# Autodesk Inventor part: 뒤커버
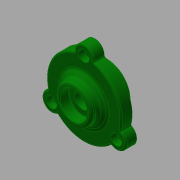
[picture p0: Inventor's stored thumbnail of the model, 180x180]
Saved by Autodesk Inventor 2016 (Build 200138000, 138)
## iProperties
Created: 2016-05
Part Number: 뒤커버
Document SubType Name: Modeling
Designer: mduedu
Density: 2.71 g/cm^3
Material: 알루미늄 6061
Appearance: 진녹색
Author: mduedu
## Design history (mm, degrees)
sketch "스케치1"
  geometry: C1 r 17.5 at (0, 0); C2 r 27.5 at (0, 0); 1 further point
  constraints: 2 centre point, 2 coincident
  dimensions: "d33" = 55 diameter of C2; "d34" = 35 diameter of C1
extrude "돌출1" new body sketch "스케치1" distance "d0" = 8; taper "d1" = 0 deg
extrude "돌출2" join sketch "스케치1" distance "d2" = 8; taper "d3" = 0 deg; dims "d35" = 9, "d36" = 0
sketch "스케치5"
  geometry: L1 (-27.5, 8)-(27.5, 8) reference; L2 (0, 0)-(0, 15); L3 (-27.5, 0)-(27.5, 0) reference; L4 (17.5, 8)-(0, 8); A1 r 25.375 centre (0, -10.375) between (17.5, 8) and (0, 15)
  constraints: 4 end point, 3 point on line, 2 point on circle, 1 centre point, 1 midpoint, 1 perpendicular
  dimensions: "d37" = 17.5 distance from line of L2 L4.start; "d39" = 7 distance from line of L1 L2.end
revolve "회전2" sketch "스케치5" stored, may be unused: angle "d40" = 90 deg
node "작업 평면1"
sketch "스케치6"
  geometry: C1 r 13.5 at (0, 0); 1 further point
  constraints: 1 centre point, 1 coincident
  dimensions: "d42" = 27 diameter of C1
extrude "돌출4" join sketch "스케치6" stored distance "d43" = 10; taper "d44" = 0 deg
sketch "스케치4"
  geometry: L1 (0, -9)-(0, 16); L2 (-15, -9)-(-15, 0); L3 (-15, 0)-(-10, 0); L4 (-10, 0)-(-10, 3); L5 (-10, 3)-(-6, 3); L6 (-6, 3)-(-6, 9); L7 (-6, 9)-(-10, 9); L8 (-10, 9)-(-10, 16); L9 (17.5, -9)-(-17.5, -9) reference; L10 (-13.5, 16)-(13.5, 16) reference; 1 further point
  constraints: 16 end point, 6 parallel, 3 point on line, 2 midpoint, 1 perpendicular, 1 vertical
  dimensions: "d15" = 30 diameter of L2 L1; "d16" = 20 diameter of L8 L1; "d18" = 9 distance of L2.start L2.end; "d19" = 3 distance of L3.end L4.end; "d20" = 20 diameter of L4 L1; "d21" = 12 diameter of L6 L1; "d45" = 7 distance of L7.end L8.end
revolve "회전1" sketch "스케치4" stored, may be unused: angle "d22" = 90 deg
fillet "모깎기2" dims "d23" = 3
fillet "모깎기3" dims "d24" = 0.3
chamfer "모따기2" distance "d46" = 0.5; stored, may be unused: second distance "d47" = 2, angle "d48" = 45 deg
fillet "모깎기4" dims "d49" = 3
fillet "모깎기5" dims "d50" = 2
sketch "스케치7"
  geometry: C1 r 7 at (0, 27.5); 2 further points
  constraints: 3 vertical alignment, 1 centre point, 2 other
  dimensions: "d54" = 14 diameter of C1
extrude "돌출5" join sketch "스케치7" stored distance "d55" = 10; taper "d56" = 0 deg
fillet "모깎기6" dims "d57" = 1
fillet "모깎기7" dims "d61" = 1
sketch "스케치8" dims "d62" = 55 (derived)
  geometry: C1 r 18.661 at (0, 0) reference; A1 r 2 centre (-7.999, 27.355) between (-7.437, 25.435) and (-5.999, 27.391) reference; A2 r 26.5 centre (0, 0) between (-7.437, 25.435) and (-25.746, -6.277) reference; A3 r 2 centre (-27.689, -6.75) between (-26.721, -8.5) and (-25.746, -6.277) reference; A4 r 6 centre (-23.816, -13.75) between (-26.721, -8.5) and (-20.722, -18.891) reference; A5 r 2 centre (-19.69, -20.604) between (-18.309, -19.158) and (-20.722, -18.891) reference; A6 r 26.5 centre (0, 0) between (-18.309, -19.158) and (18.309, -19.158) reference; A7 r 2 centre (19.69, -20.604) between (20.722, -18.891) and (18.309, -19.158) reference; A8 r 6 centre (23.816, -13.75) between (20.722, -18.891) and (26.721, -8.5) reference; A9 r 2 centre (27.689, -6.75) between (25.746, -6.277) and (26.721, -8.5) reference; A10 r 26.5 centre (0, 0) between (25.746, -6.277) and (7.437, 25.435) reference; A11 r 2 centre (7.999, 27.355) between (5.999, 27.391) and (7.437, 25.435) reference; A12 r 6 centre (0, 27.5) between (5.999, 27.391) and (-5.999, 27.391) reference; 4 further points
  constraints: 2 coincident, 1 vertical alignment, 6 other
  dimensions: "d65" = 360 deg dimension on A2.centre point (0, 27.5) (derived)
sketch "스케치9"
  geometry: 3 further points
  constraints: 3 other
hole "구멍2" sketch "스케치9" at (-23.816, -13.75), (23.816, -13.75), (0, 27.5) diameter "d67" = 4.5; stored, may be unused: countersink angle "d71" = 90 deg, drill point angle "d73" = 0 deg; dims "d68" = 6, "d69" = 8, "d70" = 4.6, "d72" = 8
node "솔리드1"
pattern_circular "원형 패턴1" dims angle "d59" = 360 deg
other parameters: "d41" = 8
